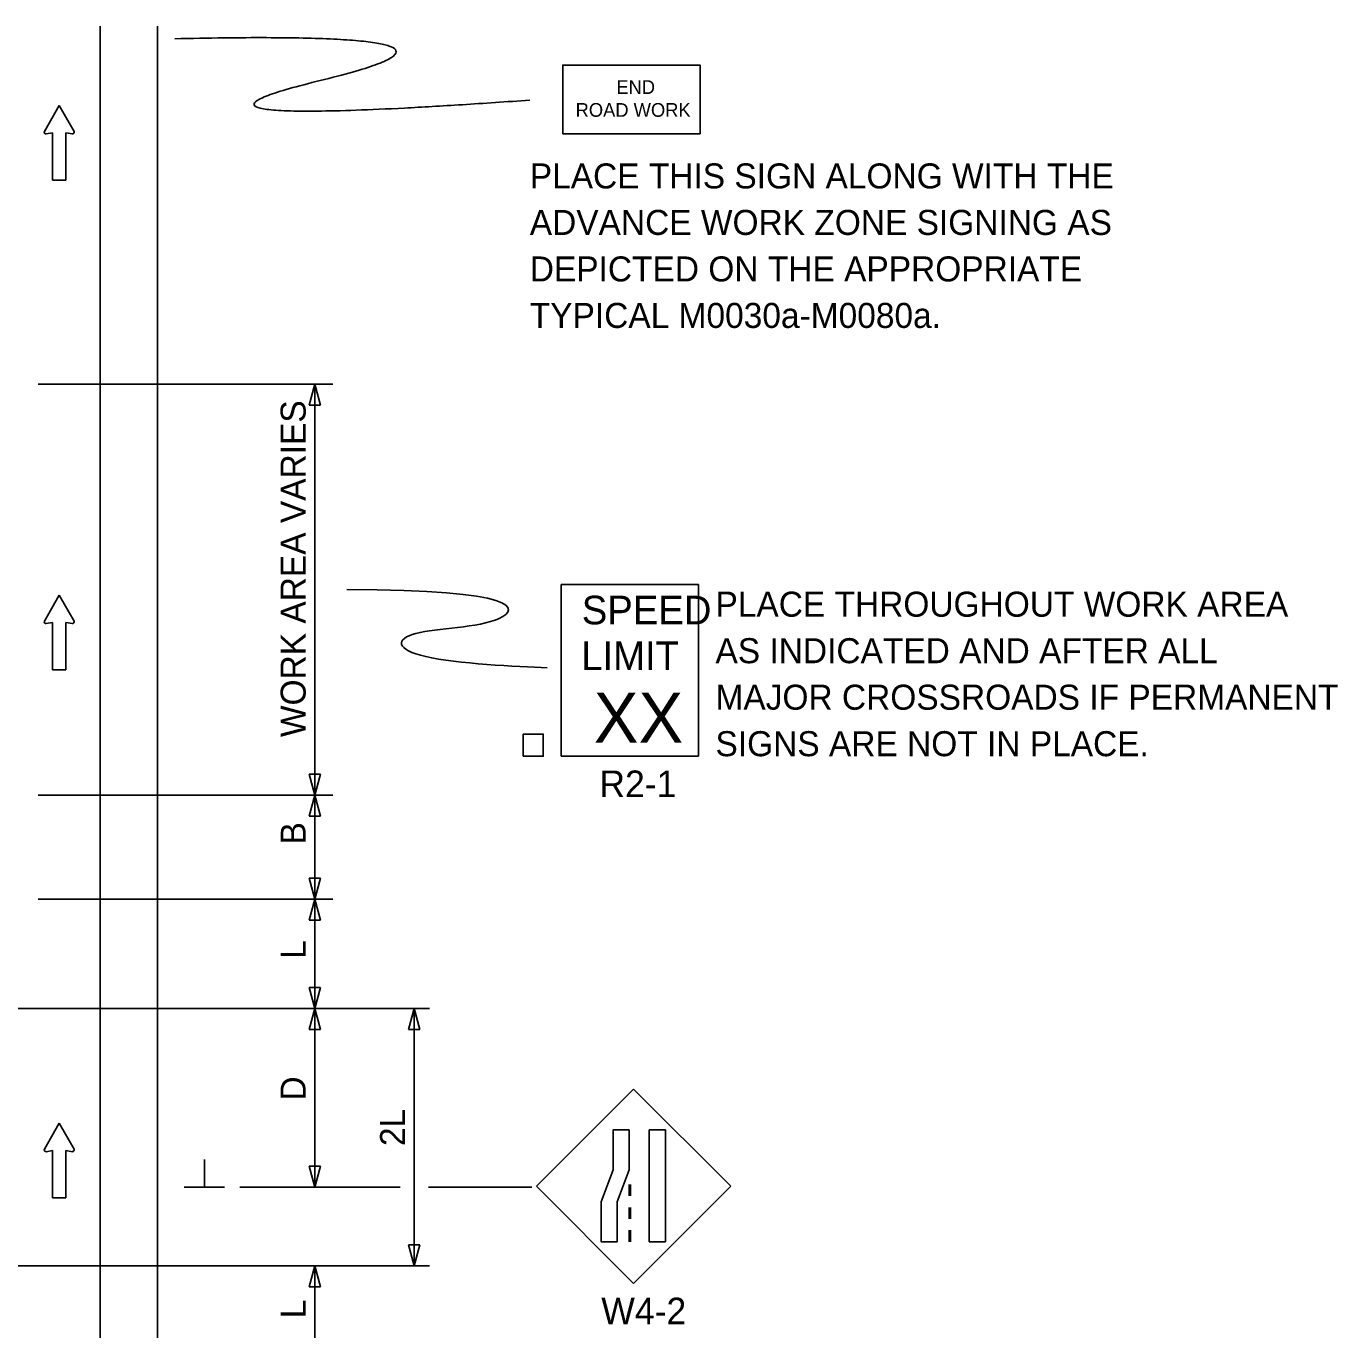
# Model space of a CAD drawing. Extents: x 16742 to 18475, y 7016 to 8203.
# Drawn here: x 17054.7 to 17421.4, y 7838.6 to 8203.1 of the extents above; entities that cross this region are included whole.
import ezdxf

# ---------------------------------------------------------------- set-up
doc = ezdxf.new("R2010")
doc.units = 0
for name, color, linetype in [('MT_SCRATCH_LEVEL_E', 7, 'Continuous'), ('PAVT_EDGE_EX', 7, 'Continuous'), ('TRAFFIC_SIGNS_PR', 7, 'Continuous'), ('TYPICAL_TEXT_DIMEN_PR', 7, 'Continuous')]:
    doc.layers.add(name, color=color, linetype=linetype)

msp = doc.modelspace()

# ---------------------------------------------------------------- linework, layer by layer
at = {"layer": 'MT_SCRATCH_LEVEL_E'}
for p, q in [((17063.89, 8180.87), (17059.78, 8173.63)), ((17063.89, 8180.87), (17059.78, 8173.63)), ((17068.04, 8173.63), (17063.89, 8180.87)), ((17068.04, 8173.63), (17063.89, 8180.87)), ((17060.26, 8172.95), (17062.04, 8173.26)), ((17060.26, 8172.95), (17062.04, 8173.26)), ((17062.04, 8173.26), (17062.04, 8160.01)), ((17062.04, 8173.26), (17062.04, 8160.01)), ((17065.78, 8160.01), (17065.78, 8173.26)), ((17065.78, 8173.26), (17067.56, 8172.95)), ((17065.78, 8160.01), (17065.78, 8173.26)), ((17065.78, 8173.26), (17067.56, 8172.95)), ((17062.04, 8160.01), (17065.78, 8160.01)), ((17062.04, 8160.01), (17065.78, 8160.01)), ((17063.89, 8043.99), (17059.78, 8036.75)), ((17063.89, 8043.99), (17059.78, 8036.75)), ((17068.04, 8036.75), (17063.89, 8043.99)), ((17068.04, 8036.75), (17063.89, 8043.99)), ((17060.26, 8036.07), (17062.04, 8036.38)), ((17060.26, 8036.07), (17062.04, 8036.38)), ((17062.04, 8036.38), (17062.04, 8023.13)), ((17062.04, 8036.38), (17062.04, 8023.13)), ((17065.78, 8023.13), (17065.78, 8036.38)), ((17065.78, 8036.38), (17067.56, 8036.07)), ((17065.78, 8023.13), (17065.78, 8036.38)), ((17065.78, 8036.38), (17067.56, 8036.07)), ((17062.04, 8023.13), (17065.78, 8023.13)), ((17062.04, 8023.13), (17065.78, 8023.13)), ((17063.89, 7896.35), (17059.78, 7889.11)), ((17063.89, 7896.35), (17059.78, 7889.11)), ((17068.04, 7889.11), (17063.89, 7896.35)), ((17068.04, 7889.11), (17063.89, 7896.35)), ((17060.26, 7888.42), (17062.04, 7888.74)), ((17060.26, 7888.42), (17062.04, 7888.74)), ((17062.04, 7888.74), (17062.04, 7875.48)), ((17062.04, 7888.74), (17062.04, 7875.48)), ((17065.78, 7875.48), (17065.78, 7888.74)), ((17065.78, 7888.74), (17067.56, 7888.42)), ((17065.78, 7875.48), (17065.78, 7888.74)), ((17065.78, 7888.74), (17067.56, 7888.42)), ((17062.04, 7875.48), (17065.78, 7875.48)), ((17062.04, 7875.48), (17065.78, 7875.48))]:
    msp.add_line(p, q, dxfattribs=at)
for centre, start, end in [((17060.19, 8173.41), 150.4248, 279.9638), ((17060.19, 8173.41), 150.4248, 279.9638), ((17067.63, 8173.41), 260.0362, 29.7731), ((17067.63, 8173.41), 260.0362, 29.7731), ((17060.19, 8036.53), 150.4248, 279.9638), ((17060.19, 8036.53), 150.4248, 279.9638), ((17067.63, 8036.53), 260.0362, 29.7731), ((17067.63, 8036.53), 260.0362, 29.7731), ((17060.19, 7888.88), 150.4248, 279.9638), ((17060.19, 7888.88), 150.4248, 279.9638), ((17067.63, 7888.88), 260.0362, 29.7731), ((17067.63, 7888.88), 260.0362, 29.7731)]:
    msp.add_arc(centre, 0.463, start, end, dxfattribs=at)
at = {"layer": 'PAVT_EDGE_EX'}
for p, q in [((17075.37, 8203.06), (17075.37, 7352.47)), ((17091.37, 8203.06), (17091.37, 7352.47))]:
    msp.add_line(p, q, dxfattribs=at)
at = {"layer": 'TRAFFIC_SIGNS_PR'}
for p, q in [((17204.26, 8046.98), (17242.66, 8046.98)), ((17204.26, 7998.98), (17204.26, 8046.98)), ((17242.66, 7998.98), (17242.66, 8046.98)), ((17204.26, 7998.98), (17242.66, 7998.98)), ((17224.51, 7905.91), (17197.36, 7878.76)), ((17251.66, 7878.76), (17224.51, 7905.91)), ((17197.36, 7878.76), (17224.51, 7851.6)), ((17223.26, 7879.25), (17223.26, 7876.05)), ((17223.66, 7879.25), (17223.66, 7876.05)), ((17224.51, 7851.6), (17251.66, 7878.76)), ((17223.26, 7872.85), (17223.26, 7869.65)), ((17223.66, 7872.85), (17223.66, 7869.65)), ((17223.26, 7866.45), (17223.26, 7863.25)), ((17223.66, 7866.45), (17223.66, 7863.25))]:
    msp.add_line(p, q, dxfattribs=at)
for points in [[(17204.69, 8173), (17243.09, 8173), (17243.09, 8192.2), (17204.69, 8192.2)], [(17193.65, 7998.98), (17199.24, 7998.98), (17199.24, 8005.15), (17193.65, 8005.15)], [(17223.26, 7894.49), (17223.26, 7883.31), (17219.92, 7874.43), (17219.92, 7863.25), (17215.43, 7863.25), (17215.43, 7874.43), (17218.77, 7883.31), (17218.77, 7894.49)], [(17233.4, 7894.49), (17233.4, 7863.25), (17228.91, 7863.25), (17228.91, 7894.49)]]:
    msp.add_lwpolyline(points, close=True, dxfattribs=at)
msp.add_open_spline([(17195.47, 8182.39), (17080.24, 8174.16), (17194.15, 8201.74), (17096.21, 8199.57)], degree=2, dxfattribs=at)
at = {"layer": 'TYPICAL_TEXT_DIMEN_PR'}
for p, q in [((17140.37, 8103.02), (17057.97, 8103.02)), ((17133.8, 8097.15), (17135.37, 8103.02)), ((17135.37, 7988.11), (17135.37, 8103.02)), ((17135.37, 8103.02), (17136.94, 8097.15)), ((17135.37, 8097.15), (17133.8, 8097.15)), ((17136.94, 8097.15), (17135.37, 8097.15)), ((17135.37, 7988.11), (17133.8, 7993.97)), ((17133.8, 7993.97), (17135.37, 7993.97)), ((17135.37, 7993.97), (17136.94, 7993.97)), ((17136.94, 7993.97), (17135.37, 7988.11)), ((17140.37, 7988.11), (17057.97, 7988.11)), ((17133.8, 7982.24), (17135.37, 7988.11)), ((17135.37, 7959.05), (17135.37, 7988.11)), ((17135.37, 7988.11), (17136.94, 7982.24)), ((17135.37, 7982.24), (17133.8, 7982.24)), ((17136.94, 7982.24), (17135.37, 7982.24)), ((17135.37, 7959.05), (17133.8, 7964.91)), ((17133.8, 7964.91), (17135.37, 7964.91)), ((17135.37, 7964.91), (17136.94, 7964.91)), ((17136.94, 7964.91), (17135.37, 7959.05)), ((17140.37, 7959.05), (17057.97, 7959.05)), ((17133.8, 7953.19), (17135.37, 7959.05)), ((17135.37, 7928.49), (17135.37, 7959.05)), ((17135.37, 7959.05), (17136.94, 7953.19)), ((17135.37, 7953.19), (17133.8, 7953.19)), ((17136.94, 7953.19), (17135.37, 7953.19)), ((17135.37, 7928.49), (17133.8, 7934.35)), ((17133.8, 7934.35), (17135.37, 7934.35)), ((17135.37, 7934.35), (17136.94, 7934.35)), ((17136.94, 7934.35), (17135.37, 7928.49)), ((17167.41, 7928.49), (17031.9, 7928.49)), ((17133.8, 7922.62), (17135.37, 7928.49)), ((17135.37, 7928.49), (17135.37, 7878.49)), ((17135.37, 7928.49), (17136.94, 7922.62)), ((17161.6, 7922.62), (17163.17, 7928.49)), ((17163.17, 7928.49), (17164.74, 7922.62)), ((17163.17, 7928.49), (17163.17, 7856.49)), ((17135.37, 7922.62), (17133.8, 7922.62)), ((17136.94, 7922.62), (17135.37, 7922.62)), ((17163.17, 7922.62), (17161.6, 7922.62)), ((17164.74, 7922.62), (17163.17, 7922.62)), ((17104.49, 7878.49), (17104.49, 7886.27)), ((17135.37, 7878.49), (17133.8, 7884.35)), ((17133.8, 7884.35), (17135.37, 7884.35)), ((17135.37, 7884.35), (17136.94, 7884.35)), ((17136.94, 7884.35), (17135.37, 7878.49)), ((17163.17, 7883.36), (17163.17, 7879.59)), ((17110.12, 7878.49), (17098.87, 7878.49)), ((17159.25, 7878.49), (17114.37, 7878.49)), ((17196.05, 7878.49), (17167.18, 7878.49)), ((17163.17, 7856.49), (17161.6, 7862.35)), ((17161.6, 7862.35), (17163.17, 7862.35)), ((17163.17, 7862.35), (17164.74, 7862.35)), ((17164.74, 7862.35), (17163.17, 7856.49)), ((17031.9, 7856.49), (17167.41, 7856.49)), ((17133.8, 7850.62), (17135.37, 7856.49)), ((17135.37, 7827.98), (17135.37, 7856.49)), ((17135.37, 7856.49), (17136.94, 7850.62)), ((17135.37, 7850.62), (17133.8, 7850.62)), ((17136.94, 7850.62), (17135.37, 7850.62))]:
    msp.add_line(p, q, dxfattribs=at)
msp.add_open_spline([(17144.29, 8045.56), (17192.75, 8045.56), (17192.75, 8034.81), (17157.84, 8034.81), (17157.84, 8025.76), (17192.04, 8024), (17200.33, 8023.71)], degree=3, dxfattribs=at)

# ---------------------------------------------------------------- texts
at = {"layer": 'TRAFFIC_SIGNS_PR'}
for s, height, p in [('END', 3.831, (17219.69, 8184.13)), ('ROAD WORK', 3.831, (17208.3, 8177.74)), ('PLACE THIS SIGN ALONG WITH THE', 7, (17195.48, 8157.71)), ('ADVANCE WORK ZONE SIGNING AS', 7, (17195.48, 8144.71)), ('DEPICTED ON THE APPROPRIATE', 7, (17195.48, 8131.71)), ('TYPICAL M0030a-M0080a.', 7, (17195.48, 8118.71)), ('SPEED', 8, (17210.02, 8035.85)), ('PLACE THROUGHOUT WORK AREA', 7, (17247.41, 8037.98)), ('AS INDICATED AND AFTER ALL', 7, (17247.41, 8024.98)), ('LIMIT', 8, (17209.86, 8023.05)), ('MAJOR CROSSROADS IF PERMANENT', 7, (17247.41, 8011.98)), ('XX', 14.031, (17213.37, 8002.74)), ('SIGNS ARE NOT IN PLACE.', 7, (17247.41, 7998.98)), ('R2-1', 7.44, (17214.93, 7987.54)), ('W4-2', 7.44, (17215.47, 7840.16))]:
    msp.add_text(s, height=height, dxfattribs=at).set_placement(p)
at = {"layer": 'TYPICAL_TEXT_DIMEN_PR'}
for s, p in [('WORK AREA VARIES', (17132.81, 8004.33)), ('B', (17132.81, 7974.31)), ('L', (17132.81, 7942.34)), ('D', (17132.81, 7902.71)), ('2L', (17160.61, 7889.99)), ('L', (17132.81, 7841.83))]:
    msp.add_text(s, height=7, rotation=90, dxfattribs=at).set_placement(p)

doc.saveas('drawing.dxf')
